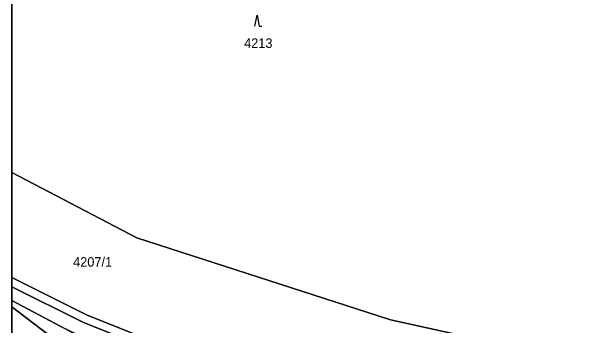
# Model space of a CAD drawing. Extents: x -598233 to -596890, y -1157848 to -1156431.
# Drawn here: x -598232.9 to -598127.8, y -1157199.2 to -1157143.3 of the extents above; entities that cross this region are included whole.
import ezdxf

# ---------------------------------------------------------------- set-up
doc = ezdxf.new("R2010")
doc.units = 0
for name, color, linetype in [('Level 1', 7, 'Continuous'), ('Level 4', 7, 'Continuous'), ('Level 5', 7, 'Continuous'), ('Vrstva 60', 7, 'Continuous'), ('zajmove_uzemi', 7, 'Continuous')]:
    doc.layers.add(name, color=color, linetype=linetype)

msp = doc.modelspace()

# ---------------------------------------------------------------- linework, layer by layer
at = {"layer": 'Level 1'}
msp.add_line((-598232.89, -1157194.81), (-598224.13, -1157199.44), dxfattribs=at)
for points in [[(-598232.89, -1157171.98), (-598210.59, -1157183.62), (-598165.35, -1157198.24), (-598123.48, -1157207.46), (-598103.14, -1157203.01), (-598084.34, -1157202.94), (-598076.6, -1157222.15), (-598061.01, -1157225.1), (-598047.25, -1157216.71), (-598051.08, -1157238.71)], [(-598232.89, -1157190.7), (-598219.56, -1157197.32), (-598179.31, -1157213.48), (-598132.24, -1157225.39), (-598076.7, -1157233.76)], [(-598076.82, -1157234.35), (-598132.41, -1157226.78), (-598179.67, -1157214.91), (-598220.23, -1157198.66), (-598232.89, -1157192.38)], [(-598232.89, -1157195.92), (-598225.15, -1157201.81), (-598207.44, -1157215.15), (-598172.49, -1157226.27)]]:
    msp.add_lwpolyline(points, dxfattribs=at)
at = {"layer": 'Level 5'}
msp.add_lwpolyline([(-598189.52, -1157145.87), (-598189.14, -1157143.87), (-598188.77, -1157145.87), (-598188.27, -1157145.87)], dxfattribs=at)
at = {"layer": 'Vrstva 60'}
for points in [[(-598232.89, -1156430.86), (-598232.89, -1157835.58), (-598232.81, -1157835.6), (-598231.24, -1157835.95), (-598223.73, -1157837.73), (-598218.75, -1157838.85), (-598190.54, -1157845.18), (-598175.89, -1157848.46), (-598170.51, -1157848.46), (-598170.38, -1157848.22), (-598166.89, -1157841.65), (-598165.3, -1157838.66), (-598164.37, -1157836.9), (-598161.86, -1157832.18), (-598161.19, -1157830.95), (-598160.05, -1157828.86), (-598157.63, -1157824.55), (-598144.71, -1157839.14), (-598136.41, -1157848.46), (-597003.66, -1157848.46)], [(-598232.89, -1157099.76), (-598232.89, -1157171.98), (-598210.59, -1157183.62), (-598165.35, -1157198.24), (-598123.48, -1157207.46), (-598103.14, -1157203.01), (-598084.34, -1157202.94), (-598076.6, -1157222.15), (-598061.01, -1157225.1), (-598047.25, -1157216.71), (-598051.08, -1157238.71), (-598039.38, -1157231.1), (-598027.68, -1157218.33), (-598020.26, -1157202.41), (-598013, -1157188.16), (-598007.71, -1157174.7), (-598007.36, -1157164.36), (-598009.87, -1157147.41), (-598011.65, -1157136.39)], [(-598225.15, -1157201.81), (-598232.89, -1157195.92), (-598232.89, -1157204.46)]]:
    msp.add_lwpolyline(points, dxfattribs=at)
for points in [[(-598232.89, -1157171.98), (-598232.89, -1157190.7), (-598219.56, -1157197.32), (-598179.31, -1157213.48), (-598132.24, -1157225.39), (-598076.7, -1157233.76), (-598076.1, -1157234.52), (-598067.89, -1157244.92), (-598067.34, -1157244.95), (-598066.54, -1157245), (-598065.85, -1157245.04), (-598060.96, -1157245.33), (-598051.58, -1157241.02), (-598051.08, -1157238.71), (-598047.25, -1157216.71), (-598061.01, -1157225.1), (-598076.6, -1157222.15), (-598084.34, -1157202.94), (-598103.14, -1157203.01), (-598123.48, -1157207.46), (-598165.35, -1157198.24), (-598210.59, -1157183.62)], [(-598232.89, -1157190.7), (-598232.89, -1157192.38), (-598220.23, -1157198.66), (-598179.67, -1157214.91), (-598132.41, -1157226.78), (-598076.82, -1157234.35), (-598076.7, -1157233.76), (-598132.24, -1157225.39), (-598179.31, -1157213.48), (-598219.56, -1157197.32)], [(-598232.89, -1157192.38), (-598232.89, -1157194.81), (-598224.13, -1157199.44), (-598165.41, -1157227.7), (-598154.86, -1157230.51), (-598134.61, -1157233.83), (-598118.18, -1157235.69), (-598111.31, -1157236.53), (-598076.98, -1157236.14), (-598069.5, -1157244.63), (-598067.89, -1157244.92), (-598076.1, -1157234.52), (-598076.7, -1157233.76), (-598076.82, -1157234.35), (-598132.41, -1157226.78), (-598179.67, -1157214.91), (-598220.23, -1157198.66)], [(-598232.89, -1157194.81), (-598232.89, -1157195.92), (-598225.15, -1157201.81), (-598207.44, -1157215.15), (-598172.49, -1157226.27), (-598185.45, -1157220.04), (-598198.66, -1157213.17), (-598224.13, -1157199.44)]]:
    msp.add_lwpolyline(points, close=True, dxfattribs=at)
at = {"layer": 'zajmove_uzemi'}
msp.add_lwpolyline([(-598232.89, -1156430.86), (-596890.46, -1156430.86), (-596890.46, -1157848.46), (-598232.89, -1157848.46)], close=True, dxfattribs=at)

# ---------------------------------------------------------------- texts
at = {"layer": 'Level 4'}
for s, p in [('4213', (-598191.45, -1157149.74)), ('4207/1', (-598221.95, -1157188.76))]:
    msp.add_text(s, height=1.7, dxfattribs=at).set_placement(p)

doc.saveas('drawing.dxf')
